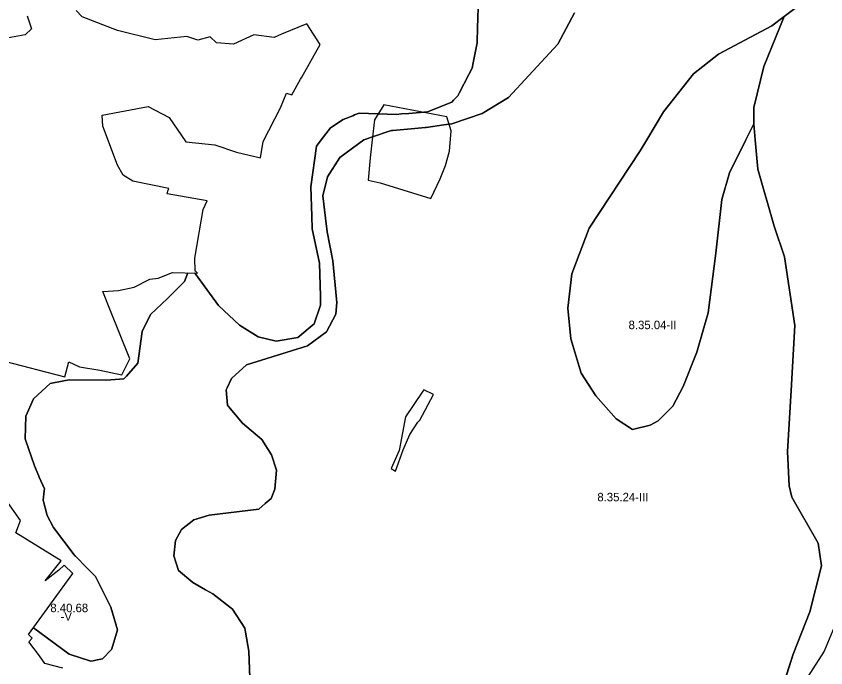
# Model space of a CAD drawing. Extents: x -547623 to -533936, y -1096714 to -1086523.
# Drawn here: x -543738 to -542784, y -1093623 to -1092854 of the extents above; entities that cross this region are included whole.
import ezdxf

# ---------------------------------------------------------------- set-up
doc = ezdxf.new("R2010")
doc.units = 0
for name, color, linetype in [('Vrstva 27', 7, 'Continuous'), ('Vrstva 28', 7, 'Continuous'), ('Vrstva 29', 7, 'Continuous')]:
    doc.layers.add(name, color=color, linetype=linetype)

msp = doc.modelspace()

# ---------------------------------------------------------------- linework, layer by layer
at = {"layer": 'Vrstva 28'}
for p, q in [((-543194.49, -1092868.4), (-543193, -1092818.5)), ((-543193, -1092818.5), (-543194.49, -1092868.4)), ((-542833, -1092854.5), (-542808.5, -1092836)), ((-542808.5, -1092836), (-542833, -1092854.5)), ((-543100, -1092887), (-543080.21, -1092850.2)), ((-543080.21, -1092850.2), (-543100, -1092887)), ((-542833, -1092854.5), (-542857, -1092913.5)), ((-542857, -1092913.5), (-542833, -1092854.5)), ((-542847.5, -1092865.5), (-542833, -1092854.5)), ((-542833, -1092854.5), (-542847.5, -1092865.5)), ((-543194.95, -1092883.97), (-543194.49, -1092868.4)), ((-543194.49, -1092868.4), (-543194.95, -1092883.97)), ((-542910.5, -1092899), (-542847.5, -1092865.5)), ((-542847.5, -1092865.5), (-542910.5, -1092899)), ((-543199.74, -1092909.19), (-543195, -1092885.5)), ((-543195, -1092885.5), (-543199.74, -1092909.19)), ((-543195, -1092885.5), (-543194.95, -1092883.97)), ((-543194.95, -1092883.97), (-543195, -1092885.5)), ((-543134.18, -1092924.12), (-543100, -1092887)), ((-543100, -1092887), (-543134.18, -1092924.12)), ((-542940, -1092922), (-542910.5, -1092899)), ((-542910.5, -1092899), (-542940, -1092922)), ((-543201, -1092915.5), (-543199.74, -1092909.19)), ((-543199.74, -1092909.19), (-543201, -1092915.5)), ((-543204.85, -1092922.97), (-543201, -1092915.5)), ((-543201, -1092915.5), (-543204.85, -1092922.97)), ((-542857, -1092913.5), (-542869, -1092962)), ((-542869, -1092962), (-542857, -1092913.5)), ((-543216.12, -1092944.82), (-543204.85, -1092922.97)), ((-543204.85, -1092922.97), (-543216.12, -1092944.82)), ((-543158, -1092950), (-543134.18, -1092924.12)), ((-543134.18, -1092924.12), (-543158, -1092950)), ((-542975.5, -1092967), (-542940, -1092922)), ((-542940, -1092922), (-542975.5, -1092967)), ((-543222.86, -1092953.22), (-543217.95, -1092947.98)), ((-543217.95, -1092947.98), (-543222.86, -1092953.22)), ((-543217.95, -1092947.98), (-543217.5, -1092947.5)), ((-543217.5, -1092947.5), (-543217.95, -1092947.98)), ((-543217.5, -1092947.5), (-543216.12, -1092944.82)), ((-543216.12, -1092944.82), (-543217.5, -1092947.5)), ((-543253.5, -1092967), (-543225, -1092955.5)), ((-543225, -1092955.5), (-543253.5, -1092967)), ((-543225, -1092955.5), (-543222.86, -1092953.22)), ((-543222.86, -1092953.22), (-543225, -1092955.5)), ((-543189, -1092969), (-543158, -1092950)), ((-543158, -1092950), (-543189, -1092969)), ((-543275.54, -1092968.81), (-543253.5, -1092967)), ((-543253.5, -1092967), (-543275.54, -1092968.81)), ((-542995, -1093000), (-542975.5, -1092967)), ((-542975.5, -1092967), (-542995, -1093000)), ((-542869, -1092962), (-542869, -1092981)), ((-542869, -1092981), (-542869, -1092962)), ((-543368, -1092986), (-543353, -1092976)), ((-543353, -1092976), (-543368, -1092986)), ((-543353, -1092976), (-543341.6, -1092971.5)), ((-543341.6, -1092971.5), (-543353, -1092976)), ((-543341.6, -1092971.5), (-543339.41, -1092970.63)), ((-543339.41, -1092970.63), (-543341.6, -1092971.5)), ((-543339.41, -1092970.63), (-543334, -1092968.5)), ((-543334, -1092968.5), (-543339.41, -1092970.63)), ((-543334, -1092968.5), (-543290, -1092970)), ((-543290, -1092970), (-543334, -1092968.5)), ((-543290, -1092970), (-543284.21, -1092969.52)), ((-543284.21, -1092969.52), (-543290, -1092970)), ((-543284.21, -1092969.52), (-543275.54, -1092968.81)), ((-543275.54, -1092968.81), (-543284.21, -1092969.52)), ((-543225, -1092981), (-543189, -1092969)), ((-543189, -1092969), (-543225, -1092981)), ((-543378.74, -1093000), (-543368, -1092986)), ((-543368, -1092986), (-543378.74, -1093000)), ((-543268.63, -1092986.66), (-543256.25, -1092985.61)), ((-543256.25, -1092985.61), (-543268.63, -1092986.66)), ((-543256.25, -1092985.61), (-543255, -1092985.5)), ((-543255, -1092985.5), (-543256.25, -1092985.61)), ((-543255, -1092985.5), (-543234.48, -1092982.42)), ((-543234.48, -1092982.42), (-543255, -1092985.5)), ((-543234.48, -1092982.42), (-543225, -1092981)), ((-543225, -1092981), (-543234.48, -1092982.42)), ((-542869, -1092981), (-542878.34, -1093000)), ((-542878.34, -1093000), (-542869, -1092981)), ((-542867.22, -1093000), (-542869, -1092981)), ((-542869, -1092981), (-542867.22, -1093000)), ((-543328.53, -1093000), (-543301.07, -1092990.71)), ((-543301.07, -1092990.71), (-543328.53, -1093000)), ((-543301.07, -1092990.71), (-543296, -1092989)), ((-543296, -1092989), (-543301.07, -1092990.71)), ((-543296, -1092989), (-543294.34, -1092988.86)), ((-543294.34, -1092988.86), (-543296, -1092989)), ((-543294.34, -1092988.86), (-543268.63, -1092986.66)), ((-543268.63, -1092986.66), (-543294.34, -1092988.86)), ((-543384.5, -1093007.5), (-543378.74, -1093000)), ((-543378.74, -1093000), (-543384.5, -1093007.5)), ((-543357, -1093021), (-543328.53, -1093000)), ((-543328.53, -1093000), (-543357, -1093021)), ((-543003, -1093013), (-542995, -1093000)), ((-542995, -1093000), (-543003, -1093013)), ((-542878.34, -1093000), (-542897.5, -1093039)), ((-542897.5, -1093039), (-542878.34, -1093000)), ((-542864, -1093034.5), (-542867.22, -1093000)), ((-542867.22, -1093000), (-542864, -1093034.5)), ((-543391, -1093055.5), (-543384.5, -1093007.5)), ((-543384.5, -1093007.5), (-543391, -1093055.5)), ((-543063, -1093104), (-543003, -1093013)), ((-543003, -1093013), (-543063, -1093104)), ((-543371.5, -1093043.5), (-543357, -1093021)), ((-543357, -1093021), (-543371.5, -1093043.5)), ((-543377, -1093066), (-543371.5, -1093043.5)), ((-543371.5, -1093043.5), (-543377, -1093066)), ((-542897.5, -1093039), (-542906.5, -1093070.5)), ((-542906.5, -1093070.5), (-542897.5, -1093039)), ((-542845, -1093102), (-542864, -1093034.5)), ((-542864, -1093034.5), (-542845, -1093102)), ((-543389.96, -1093089.91), (-543391, -1093055.5)), ((-543391, -1093055.5), (-543389.96, -1093089.91)), ((-543373.88, -1093092.49), (-543377, -1093066)), ((-543377, -1093066), (-543373.88, -1093092.49)), ((-542906.5, -1093070.5), (-542913.5, -1093133.5)), ((-542913.5, -1093133.5), (-542906.5, -1093070.5)), ((-543389.5, -1093105), (-543389.96, -1093089.91)), ((-543389.96, -1093089.91), (-543389.5, -1093105)), ((-543372, -1093108.5), (-543373.88, -1093092.49)), ((-543373.88, -1093092.49), (-543372, -1093108.5)), ((-543381, -1093145.5), (-543389.5, -1093105)), ((-543389.5, -1093105), (-543381, -1093145.5)), ((-543365, -1093142.5), (-543372, -1093108.5)), ((-543372, -1093108.5), (-543365, -1093142.5)), ((-543083.5, -1093158), (-543063, -1093104)), ((-543063, -1093104), (-543083.5, -1093158)), ((-542832.5, -1093138), (-542845, -1093102)), ((-542845, -1093102), (-542832.5, -1093138)), ((-542913.5, -1093133.5), (-542922.5, -1093204)), ((-542922.5, -1093204), (-542913.5, -1093133.5)), ((-542820.5, -1093219), (-542832.5, -1093138)), ((-542832.5, -1093138), (-542820.5, -1093219)), ((-543379.82, -1093184.45), (-543381, -1093145.5)), ((-543381, -1093145.5), (-543379.82, -1093184.45)), ((-543360.86, -1093188.09), (-543365, -1093142.5)), ((-543365, -1093142.5), (-543360.86, -1093188.09)), ((-543540, -1093167), (-543536.22, -1093156.91)), ((-543536.22, -1093156.91), (-543540, -1093167)), ((-543528.26, -1093157.2), (-543527.5, -1093157.5)), ((-543527.5, -1093157.5), (-543528.26, -1093157.2)), ((-543527.5, -1093157.5), (-543500, -1093195.5)), ((-543500, -1093195.5), (-543527.5, -1093157.5)), ((-543088, -1093198.5), (-543083.5, -1093158)), ((-543083.5, -1093158), (-543088, -1093198.5)), ((-543560, -1093187), (-543540, -1093167)), ((-543540, -1093167), (-543560, -1093187)), ((-543379.5, -1093195), (-543379.82, -1093184.45)), ((-543379.82, -1093184.45), (-543379.5, -1093195)), ((-543580, -1093206), (-543560, -1093187)), ((-543560, -1093187), (-543580, -1093206)), ((-543500, -1093195.5), (-543475, -1093218.5)), ((-543475, -1093218.5), (-543500, -1093195.5)), ((-543387, -1093217), (-543379.5, -1093195)), ((-543379.5, -1093195), (-543387, -1093217)), ((-543361.5, -1093205.5), (-543360.5, -1093192)), ((-543360.5, -1093192), (-543361.5, -1093205.5)), ((-543360.5, -1093192), (-543360.86, -1093188.09)), ((-543360.86, -1093188.09), (-543360.5, -1093192)), ((-543590, -1093226), (-543580, -1093206)), ((-543580, -1093206), (-543590, -1093226)), ((-543372.5, -1093226.5), (-543361.5, -1093205.5)), ((-543361.5, -1093205.5), (-543372.5, -1093226.5)), ((-543084.5, -1093234.5), (-543088, -1093198.5)), ((-543088, -1093198.5), (-543084.5, -1093234.5)), ((-542922.5, -1093204), (-542936, -1093250.5)), ((-542936, -1093250.5), (-542922.5, -1093204)), ((-543475, -1093218.5), (-543453, -1093232.5)), ((-543453, -1093232.5), (-543475, -1093218.5)), ((-543406.5, -1093233), (-543387, -1093217)), ((-543387, -1093217), (-543406.5, -1093233)), ((-542825, -1093295.5), (-542820.5, -1093219)), ((-542820.5, -1093219), (-542825, -1093295.5)), ((-543595, -1093263.5), (-543590, -1093226)), ((-543590, -1093226), (-543595, -1093263.5)), ((-543453, -1093232.5), (-543432, -1093237.5)), ((-543432, -1093237.5), (-543453, -1093232.5)), ((-543432, -1093237.5), (-543406.5, -1093233)), ((-543406.5, -1093233), (-543432, -1093237.5)), ((-543395, -1093243), (-543372.5, -1093226.5)), ((-543372.5, -1093226.5), (-543395, -1093243)), ((-543072.5, -1093275), (-543084.5, -1093234.5)), ((-543084.5, -1093234.5), (-543072.5, -1093275)), ((-543467, -1093265.5), (-543395, -1093243)), ((-543395, -1093243), (-543467, -1093265.5)), ((-542936, -1093250.5), (-542952, -1093291)), ((-542952, -1093291), (-542936, -1093250.5)), ((-543608.47, -1093278.6), (-543595.02, -1093263.52)), ((-543595.02, -1093263.52), (-543608.47, -1093278.6)), ((-543595.02, -1093263.52), (-543595, -1093263.5)), ((-543595, -1093263.5), (-543595.02, -1093263.52)), ((-543484.5, -1093281.5), (-543467, -1093265.5)), ((-543467, -1093265.5), (-543484.5, -1093281.5)), ((-543632, -1093283.5), (-543611.5, -1093282)), ((-543611.5, -1093282), (-543632, -1093283.5)), ((-543611.5, -1093282), (-543608.47, -1093278.6)), ((-543608.47, -1093278.6), (-543611.5, -1093282)), ((-543489.8, -1093292.5), (-543484.5, -1093281.5)), ((-543484.5, -1093281.5), (-543489.8, -1093292.5)), ((-543055, -1093302), (-543072.5, -1093275)), ((-543072.5, -1093275), (-543055, -1093302)), ((-543718, -1093305.5), (-543698.5, -1093287.5)), ((-543698.5, -1093287.5), (-543718, -1093305.5)), ((-543698.5, -1093287.5), (-543682.3, -1093284.26)), ((-543682.3, -1093284.26), (-543698.5, -1093287.5)), ((-543682.3, -1093284.26), (-543676, -1093283)), ((-543676, -1093283), (-543682.3, -1093284.26)), ((-543676, -1093283), (-543632, -1093283.5)), ((-543632, -1093283.5), (-543676, -1093283)), ((-542952, -1093291), (-542964.5, -1093314)), ((-542964.5, -1093314), (-542952, -1093291)), ((-543491, -1093295), (-543489.8, -1093292.5)), ((-543489.8, -1093292.5), (-543491, -1093295)), ((-543489.5, -1093313), (-543491, -1093295)), ((-543491, -1093295), (-543489.5, -1093313)), ((-543259.13, -1093296.38), (-543279.3, -1093326.83)), ((-542829, -1093367.5), (-542825, -1093295.5)), ((-542825, -1093295.5), (-542829, -1093367.5)), ((-543727, -1093326), (-543718, -1093305.5)), ((-543718, -1093305.5), (-543727, -1093326)), ((-543031, -1093329), (-543055, -1093302)), ((-543055, -1093302), (-543031, -1093329)), ((-543488.2, -1093314.52), (-543489.5, -1093313)), ((-543489.5, -1093313), (-543488.2, -1093314.52)), ((-543471.5, -1093334), (-543488.2, -1093314.52)), ((-543488.2, -1093314.52), (-543471.5, -1093334)), ((-542964.5, -1093314), (-542981.5, -1093331.5)), ((-542981.5, -1093331.5), (-542964.5, -1093314)), ((-543728, -1093352.5), (-543727, -1093326)), ((-543727, -1093326), (-543728, -1093352.5)), ((-543012, -1093341.5), (-543031, -1093329)), ((-543031, -1093329), (-543012, -1093341.5)), ((-543449, -1093353.5), (-543471.5, -1093334)), ((-543471.5, -1093334), (-543449, -1093353.5)), ((-542991, -1093336.5), (-543012, -1093341.5)), ((-543012, -1093341.5), (-542991, -1093336.5)), ((-542981.5, -1093331.5), (-542991, -1093336.5)), ((-542991, -1093336.5), (-542981.5, -1093331.5)), ((-543717, -1093384.5), (-543728, -1093352.5)), ((-543728, -1093352.5), (-543717, -1093384.5)), ((-543437.5, -1093371.5), (-543449, -1093353.5)), ((-543449, -1093353.5), (-543437.5, -1093371.5)), ((-542827, -1093408), (-542829, -1093367.5)), ((-542829, -1093367.5), (-542827, -1093408)), ((-543431.5, -1093389.5), (-543437.5, -1093371.5)), ((-543437.5, -1093371.5), (-543431.5, -1093389.5)), ((-543711.67, -1093396.5), (-543717, -1093384.5)), ((-543717, -1093384.5), (-543711.67, -1093396.5)), ((-543711.14, -1093397.69), (-543711.67, -1093396.5)), ((-543711.67, -1093396.5), (-543711.14, -1093397.69)), ((-543433.5, -1093412), (-543431.5, -1093389.5)), ((-543431.5, -1093389.5), (-543433.5, -1093412)), ((-543705, -1093411.5), (-543711.14, -1093397.69)), ((-543711.14, -1093397.69), (-543705, -1093411.5)), ((-543706.5, -1093425), (-543705.27, -1093413.92)), ((-543705.27, -1093413.92), (-543706.5, -1093425)), ((-543705.27, -1093413.92), (-543705, -1093411.5)), ((-543705, -1093411.5), (-543705.27, -1093413.92)), ((-543438, -1093423), (-543433.5, -1093412)), ((-543433.5, -1093412), (-543438, -1093423)), ((-542824, -1093421.5), (-542827, -1093408)), ((-542827, -1093408), (-542824, -1093421.5)), ((-543702, -1093443), (-543706.5, -1093425)), ((-543706.5, -1093425), (-543702, -1093443)), ((-543444.95, -1093428.99), (-543438, -1093423)), ((-543438, -1093423), (-543444.95, -1093428.99)), ((-542793, -1093475.5), (-542824, -1093421.5)), ((-542824, -1093421.5), (-542793, -1093475.5)), ((-543452.5, -1093435.5), (-543444.95, -1093428.99)), ((-543444.95, -1093428.99), (-543452.5, -1093435.5)), ((-543694.5, -1093457), (-543702, -1093443)), ((-543702, -1093443), (-543694.5, -1093457)), ((-543529, -1093448), (-543511, -1093442.5)), ((-543511, -1093442.5), (-543529, -1093448)), ((-543511, -1093442.5), (-543452.5, -1093435.5)), ((-543452.5, -1093435.5), (-543511, -1093442.5)), ((-543543.5, -1093459.5), (-543529, -1093448)), ((-543529, -1093448), (-543543.5, -1093459.5)), ((-543670.03, -1093489.3), (-543694.5, -1093457)), ((-543694.5, -1093457), (-543670.03, -1093489.3)), ((-543550.5, -1093472.5), (-543543.5, -1093459.5)), ((-543543.5, -1093459.5), (-543550.5, -1093472.5)), ((-543552.5, -1093490.5), (-543550.5, -1093472.5)), ((-543550.5, -1093472.5), (-543552.5, -1093490.5)), ((-542789, -1093502.5), (-542793, -1093475.5)), ((-542793, -1093475.5), (-542789, -1093502.5)), ((-543669.5, -1093490), (-543670.03, -1093489.3)), ((-543670.03, -1093489.3), (-543669.5, -1093490)), ((-543668.61, -1093490.9), (-543669.5, -1093490)), ((-543669.5, -1093490), (-543668.61, -1093490.9)), ((-543654.77, -1093505.03), (-543668.61, -1093490.9)), ((-543668.61, -1093490.9), (-543654.77, -1093505.03)), ((-543547, -1093508), (-543552.5, -1093490.5)), ((-543552.5, -1093490.5), (-543547, -1093508)), ((-543645.7, -1093514.28), (-543654.77, -1093505.03)), ((-543654.77, -1093505.03), (-543645.7, -1093514.28)), ((-543530, -1093522), (-543547, -1093508)), ((-543547, -1093508), (-543530, -1093522)), ((-542803, -1093556.5), (-542789, -1093502.5)), ((-542789, -1093502.5), (-542803, -1093556.5)), ((-543645, -1093515), (-543645.7, -1093514.28)), ((-543645.7, -1093514.28), (-543645, -1093515)), ((-543627, -1093551), (-543645, -1093515)), ((-543645, -1093515), (-543627, -1093551)), ((-543515.16, -1093530.53), (-543530, -1093522)), ((-543530, -1093522), (-543515.16, -1093530.53)), ((-543506.5, -1093535.5), (-543515.16, -1093530.53)), ((-543515.16, -1093530.53), (-543506.5, -1093535.5)), ((-543483.5, -1093553.5), (-543506.5, -1093535.5)), ((-543506.5, -1093535.5), (-543483.5, -1093553.5)), ((-543619, -1093578), (-543627, -1093551)), ((-543627, -1093551), (-543619, -1093578)), ((-543469, -1093576), (-543483.5, -1093553.5)), ((-543483.5, -1093553.5), (-543469, -1093576)), ((-542822.5, -1093606.5), (-542803, -1093556.5)), ((-542803, -1093556.5), (-542822.5, -1093606.5)), ((-543718.03, -1093575.3), (-543676, -1093606.5)), ((-543676, -1093606.5), (-543718.03, -1093575.3)), ((-543625.82, -1093600.4), (-543619, -1093578)), ((-543619, -1093578), (-543625.82, -1093600.4)), ((-543468.14, -1093580.66), (-543469, -1093576)), ((-543469, -1093576), (-543468.14, -1093580.66)), ((-543464, -1093603), (-543468.14, -1093580.66)), ((-543468.14, -1093580.66), (-543464, -1093603)), ((-543676, -1093606.5), (-543650.5, -1093615)), ((-543650.5, -1093615), (-543676, -1093606.5)), ((-543636.5, -1093612), (-543626, -1093601)), ((-543626, -1093601), (-543636.5, -1093612)), ((-543626, -1093601), (-543625.82, -1093600.4)), ((-543625.82, -1093600.4), (-543626, -1093601)), ((-543462.5, -1093652.5), (-543464, -1093603)), ((-543464, -1093603), (-543462.5, -1093652.5)), ((-542844, -1093673.5), (-542822.5, -1093606.5)), ((-542822.5, -1093606.5), (-542844, -1093673.5)), ((-543650.5, -1093615), (-543647.8, -1093614.42)), ((-543647.8, -1093614.42), (-543650.5, -1093615)), ((-543647.8, -1093614.42), (-543643.06, -1093613.41)), ((-543643.06, -1093613.41), (-543647.8, -1093614.42)), ((-543643.06, -1093613.41), (-543642.64, -1093613.32)), ((-543642.64, -1093613.32), (-543643.06, -1093613.41)), ((-543642.64, -1093613.32), (-543636.5, -1093612)), ((-543636.5, -1093612), (-543642.64, -1093613.32))]:
    msp.add_line(p, q, dxfattribs=at)
for points in [[(-542844, -1093673.5), (-542822.5, -1093606.5), (-542803, -1093556.5), (-542789, -1093502.5), (-542793, -1093475.5), (-542824, -1093421.5), (-542827, -1093408), (-542829, -1093367.5), (-542825, -1093295.5), (-542820.5, -1093219), (-542832.5, -1093138), (-542845, -1093102), (-542864, -1093034.5), (-542867.22, -1093000), (-542869, -1092981), (-542878.34, -1093000), (-542897.5, -1093039), (-542906.5, -1093070.5), (-542913.5, -1093133.5), (-542922.5, -1093204), (-542936, -1093250.5), (-542952, -1093291), (-542964.5, -1093314), (-542981.5, -1093331.5), (-542991, -1093336.5), (-543012, -1093341.5), (-543031, -1093329), (-543055, -1093302), (-543072.5, -1093275), (-543084.5, -1093234.5), (-543088, -1093198.5), (-543083.5, -1093158), (-543063, -1093104), (-543003, -1093013), (-542995, -1093000), (-542975.5, -1092967), (-542940, -1092922), (-542910.5, -1092899), (-542847.5, -1092865.5), (-542833, -1092854.5), (-542808.5, -1092836)], [(-543753.78, -1093260.76), (-543681.01, -1093279.31), (-543676.35, -1093261.71), (-543663.84, -1093267.81), (-543639.69, -1093271.57), (-543613.72, -1093277.12), (-543605.36, -1093259.95), (-543604.6, -1093258.38), (-543627.89, -1093199.7), (-543636.33, -1093178.69), (-543617.68, -1093177.61), (-543599.19, -1093173.63), (-543580.96, -1093164.48), (-543571, -1093163.1), (-543554.22, -1093156.26), (-543524.58, -1093157.33), (-543527.01, -1093154.91), (-543527.54, -1093154.82), (-543527.95, -1093139.72), (-543518.18, -1093081.98), (-543513.34, -1093072.12), (-543560.54, -1093063.56), (-543559.6, -1093060.52), (-543558.66, -1093057.46), (-543600.9, -1093048.71), (-543612.21, -1093041.73), (-543618.98, -1093029.69), (-543636.38, -1092983.84), (-543637.04, -1092970.94), (-543582.78, -1092960.52), (-543558.2, -1092973.61), (-543538.55, -1093002.46), (-543504.22, -1093005.95), (-543478.74, -1093014.39), (-543450.49, -1093021.07), (-543447.12, -1093002.09), (-543426.74, -1092962.36), (-543419.61, -1092944.9), (-543413.34, -1092946.78), (-543403.18, -1092928.63), (-543401.77, -1092926.12), (-543380.26, -1092887.65), (-543395.98, -1092863.2), (-543425.64, -1092875.51), (-543434.22, -1092879.16), (-543458.08, -1092876.18), (-543482.41, -1092887.18), (-543502.45, -1092885.74), (-543509.79, -1092878.43), (-543524.1, -1092882.48), (-543537.32, -1092878.05), (-543574.64, -1092882.2), (-543618.81, -1092871.11), (-543660.75, -1092854.95), (-543667.66, -1092847.48)], [(-543080.21, -1092850.2), (-543100, -1092887), (-543134.18, -1092924.12), (-543158, -1092950), (-543189, -1092969), (-543225, -1092981), (-543234.48, -1092982.42), (-543255, -1092985.5), (-543256.25, -1092985.61), (-543268.63, -1092986.66), (-543294.34, -1092988.86), (-543296, -1092989), (-543301.07, -1092990.71), (-543328.53, -1093000), (-543357, -1093021), (-543371.5, -1093043.5), (-543377, -1093066), (-543373.88, -1093092.49), (-543372, -1093108.5), (-543365, -1093142.5), (-543360.86, -1093188.09), (-543360.5, -1093192), (-543361.5, -1093205.5), (-543372.5, -1093226.5), (-543395, -1093243), (-543467, -1093265.5), (-543484.5, -1093281.5), (-543489.8, -1093292.5), (-543491, -1093295), (-543489.5, -1093313), (-543488.2, -1093314.52), (-543471.5, -1093334), (-543449, -1093353.5), (-543437.5, -1093371.5), (-543431.5, -1093389.5), (-543433.5, -1093412), (-543438, -1093423), (-543444.95, -1093428.99), (-543452.5, -1093435.5), (-543511, -1093442.5), (-543529, -1093448), (-543543.5, -1093459.5), (-543550.5, -1093472.5), (-543552.5, -1093490.5), (-543547, -1093508), (-543530, -1093522), (-543515.16, -1093530.53), (-543506.5, -1093535.5), (-543483.5, -1093553.5), (-543469, -1093576), (-543468.14, -1093580.66), (-543464, -1093603), (-543462.5, -1093652.5)], [(-543725.53, -1092853.86), (-543724.81, -1092856.1), (-543720.38, -1092869.15), (-543727.83, -1092876.02), (-543753.88, -1092881.02)], [(-543003, -1093013), (-543063, -1093104), (-543083.5, -1093158), (-543088, -1093198.5), (-543084.5, -1093234.5), (-543072.5, -1093275), (-543055, -1093302), (-543031, -1093329), (-543012, -1093341.5), (-542991, -1093336.5), (-542981.5, -1093331.5), (-542964.5, -1093314), (-542952, -1093291), (-542936, -1093250.5), (-542922.5, -1093204), (-542913.5, -1093133.5), (-542906.5, -1093070.5), (-542897.5, -1093039), (-542878.34, -1093000), (-542869, -1092981), (-542869, -1092962), (-542857, -1092913.5), (-542833, -1092854.5), (-542847.5, -1092865.5), (-542910.5, -1092899), (-542940, -1092922), (-542975.5, -1092967), (-542995, -1093000), (-543003, -1093013)], [(-543259.13, -1093296.38), (-543259.13, -1093296.38), (-543279.3, -1093326.83), (-543286.78, -1093366.18), (-543296.49, -1093387.58), (-543291.45, -1093390.89), (-543282.29, -1093365.7), (-543274.52, -1093347.36), (-543264.81, -1093332.82), (-543262.61, -1093330.72), (-543246.62, -1093300.52), (-543257.99, -1093294.66), (-543259.13, -1093296.38)], [(-543683.55, -1093623.02), (-543704.77, -1093617.4), (-543711.01, -1093608.58), (-543723.42, -1093591.87), (-543719.78, -1093587.84), (-543723.86, -1093583.35), (-543671.71, -1093511.39), (-543681.79, -1093501.66), (-543688.15, -1093507.62), (-543704.14, -1093519.96), (-543685.56, -1093496.59), (-543738.79, -1093463.49), (-543733.22, -1093448.93), (-543752.96, -1093421.2)]]:
    msp.add_lwpolyline(points, dxfattribs=at)
at = {"layer": 'Vrstva 29'}
for points in [[(-543238.52, -1093045.83), (-543232.23, -1093030.38), (-543227.79, -1093013.19), (-543225.45, -1092989.37), (-543230.82, -1092972.91), (-543305.03, -1092958.68), (-543316.18, -1092976.42), (-543318.75, -1092999.95), (-543321.32, -1093021.18), (-543323.44, -1093047.59), (-543309.19, -1093050.68), (-543249.52, -1093069.21), (-543238.52, -1093045.83)], [(-542769.26, -1093663.94), (-542767.9, -1093639.76), (-542771.55, -1093614.52), (-542774.09, -1093574.55), (-542785.9, -1093602.97), (-542812.72, -1093644.61), (-542832.55, -1093662.16), (-542858.95, -1093685.92), (-542838.19, -1093713.79), (-542824.85, -1093737.01), (-542803.2, -1093759.09), (-542796.93, -1093732.12), (-542792.54, -1093703.66), (-542799.47, -1093666.28), (-542783.26, -1093677.26), (-542771.65, -1093683.4), (-542769.26, -1093663.94)]]:
    msp.add_lwpolyline(points, dxfattribs=at)

# ---------------------------------------------------------------- texts
at = {"layer": 'Vrstva 27'}
for s, p in [('8.35.04-II', (-543016.5, -1093223.28)), ('8.35.24-III', (-543053.31, -1093426.29)), ('8.40.68', (-543698.18, -1093557.04)), ('-V', (-543686.05, -1093567.04))]:
    msp.add_text(s, height=10, dxfattribs=at).set_placement(p)

doc.saveas('drawing.dxf')
